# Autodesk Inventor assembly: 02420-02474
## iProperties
Author: Administrator
Shininess: 64.0
Angle Display Precision: 2
Document Length Units: 11272
Document Angle Units: 11286
Document Time Units: 11279
Document Mass Units: 11290
Document Length Units Precision: 3
Document Angle Units Precision: 2
Compacted: True
PropertySet Name: _Private Model Information
Created: 2002-04
Part Number: 02420-02474
Document SubType Name: Assembly
Designer: Administrator
Control State: 0
Master: False
Checked Out: False
PropertySet Name: Design Tracking Control
Density: 0.0
Volumn: 0.0
Area: 0.0
PropertySet Name: Model Information
